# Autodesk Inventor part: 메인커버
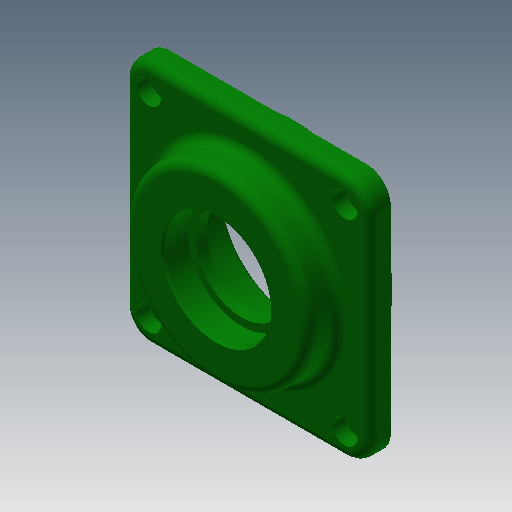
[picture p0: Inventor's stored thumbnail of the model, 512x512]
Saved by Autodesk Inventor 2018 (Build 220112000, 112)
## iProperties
Created: 2018-09
Part Number: 메인커버
Material: 알루미늄 6061
Document SubType Name: Modeling
Designer: mduedu
Density: 2.71 g/cm^3
Mass: 178.463 g
Surface Area: 197.883 cm^2
Volume: 65.8536 cm^3
Appearance: 진녹색
Author: mduedu
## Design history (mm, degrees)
sketch "스케치1"
  geometry: L1 (-40, -40)-(40, -40); L2 (40, -40)-(40, 40); L3 (40, 40)-(-40, 40); L4 (-40, 40)-(-40, -40); L5 (-40, -40)-(40, 40); L6 (40, -40)-(-40, 40); 1 further point
  constraints: 12 end point, 2 midpoint, 2 parallel, 1 horizontal, 1 perpendicular
  dimensions: "d0" = 80 distance of L3.end L2.end; "d1" = 80 distance of L2.end L1.end
extrude "돌출1" new body sketch "스케치1" distance "d2" = 7; taper "d3" = 0 deg
sketch "스케치2"
  geometry: C1 r 30 at (0, 0); 1 further point
  constraints: 1 centre point, 1 coincident
  dimensions: "d4" = 60 diameter of C1
extrude "돌출2" join sketch "스케치2" distance "d5" = 10; taper "d6" = 0 deg
sketch "스케치3"
  geometry: C1 r 32.5 at (0, 0); 1 further point
  constraints: 1 centre point, 1 coincident
  dimensions: "d7" = 65 diameter of C1
extrude "돌출3" join sketch "스케치3" distance "d8" = 9; taper "d9" = 0 deg
sketch "스케치4"
  geometry: L1 (-32.5, -9)-(32.5, -9) reference; L2 (30, 17)-(-30, 17) reference; L3 (0, 17)-(0, -9); L4 (0, -9)-(23.5, -9); L5 (23.5, -9)-(23.5, 5); L6 (23.5, 5)-(0, 5); L7 (0, 5)-(0, -9); L8 (0, 5)-(15, 5); L9 (15, 5)-(15, 8.7); L10 (15, 8.7)-(0, 8.7); L11 (0, 8.7)-(0, 5); L12 (0, 8.7)-(17.5, 8.7); L13 (17.5, 8.7)-(17.5, 17); L14 (17.5, 17)-(0, 17); L15 (0, 17)-(0, 8.7); 1 further point
  constraints: 26 end point, 6 parallel, 3 horizontal, 3 perpendicular, 2 midpoint, 1 point on line
  dimensions: "d10" = 14 distance of L4.end L5.end; "d12" = 8.3 distance of L12.end L13.end; "d13" = 35 diameter of L13 L3; "d14" = 30 diameter of L9 L3; "d15" = 47 diameter of L5 L3
revolve "회전1" sketch "스케치4" stored, may be unused: angle "d16" = 90 deg
fillet "모깎기1" dims "d17" = 8
fillet "모깎기2" dims "d18" = 3
fillet "모깎기3" dims "d19" = 3
chamfer "모따기1" distance "d20" = 0.8; stored, may be unused: second distance "d21" = 2, angle "d22" = 30 deg
chamfer "모따기2" distance "d23" = 1; stored, may be unused: second distance "d24" = 2, angle "d25" = 30 deg
fillet "모깎기4" dims "d26" = 0.3
sketch "스케치5"
  geometry: A1 r 8 centre (-32, 32) between (-32, 40) and (-40, 32) reference; A2 r 8 centre (-32, -32) between (-40, -32) and (-32, -40) reference; A3 r 8 centre (32, -32) between (32, -40) and (40, -32) reference; A4 r 8 centre (32, 32) between (40, 32) and (32, 40) reference; 5 further points
  constraints: 4 coincident
hole "구멍1" sketch "스케치5" at (-32, 32), (32, 32), (32, -32), (-32, -32) diameter "d27" = 4.5; stored, may be unused: countersink angle "d31" = 90 deg, drill point angle "d33" = 118 deg; dims "d28" = 6, "d29" = 8, "d30" = 4.4, "d32" = 8
node "솔리드1"
